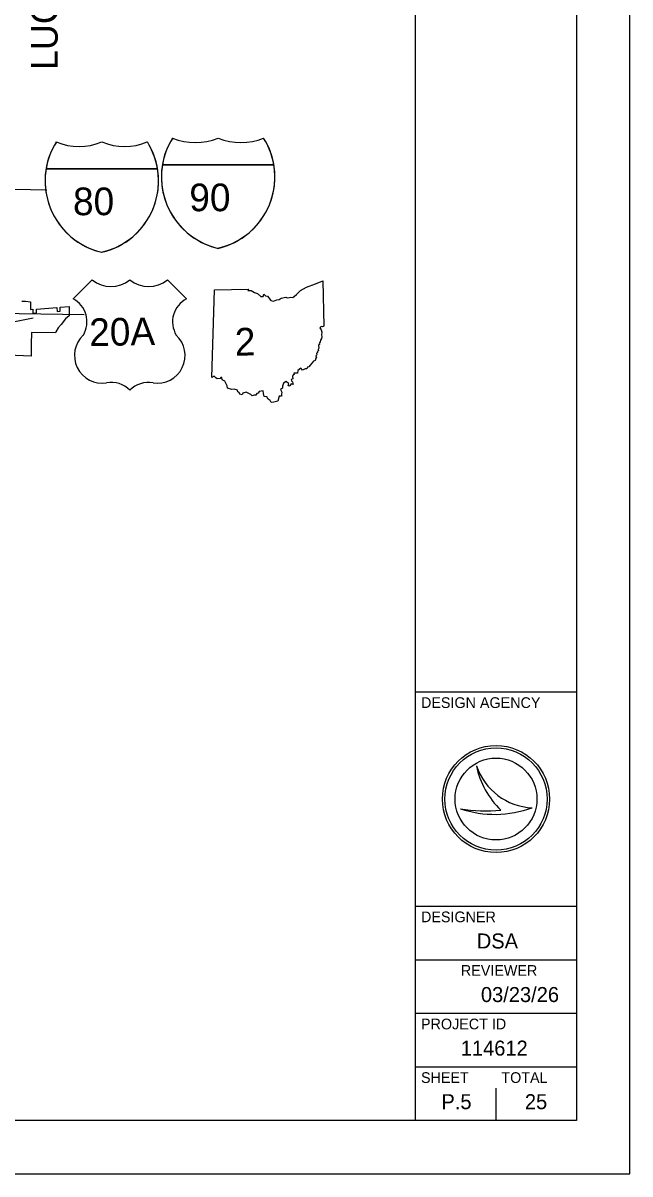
# Model space of a CAD drawing. Extents: x 0 to 849, y 0 to 440.
# Drawn here: x 566.7 to 680, y 0 to 214.9 of the extents above; entities that cross this region are included whole.
import ezdxf

# ---------------------------------------------------------------- set-up
doc = ezdxf.new("R2010")
doc.units = 0
for name, color, linetype in [('DV_X_Corp_Line', 7, 'Continuous'), ('GM_X_Adjacent_County_Text', 7, 'Continuous'), ('GM_X_Interstate_Route', 7, 'Continuous'), ('PV_P_Walk', 7, 'Continuous'), ('RD_X_RR_2', 7, 'Continuous'), ('SH_Border', 7, 'Continuous'), ('SH_Cut_Line', 7, 'Continuous'), ('SH_Data', 7, 'Continuous')]:
    doc.layers.add(name, color=color, linetype=linetype)

msp = doc.modelspace()

# ---------------------------------------------------------------- linework, layer by layer
at = {"layer": 'DV_X_Corp_Line'}
msp.add_lwpolyline([(566.48, 162.95), (567.15, 162.94), (568.14, 162.83), (568.14, 161.4), (568.57, 161.43), (568.56, 160.72), (569.22, 160.79), (569.23, 161.48), (573.02, 161.79), (573.07, 161.04), (573.63, 161.08), (573.62, 161.83), (575.3, 161.96), (575.35, 160.22), (574.62, 159.66), (573.81, 158.59), (573.26, 157.94), (572.82, 157.24), (572.76, 157.04), (568.3, 157.09), (568.26, 154.94), (568.24, 152.7), (563.91, 152.84)], dxfattribs=at)
at = {"layer": 'GM_X_Interstate_Route'}
for p, q in [((560.35, 183.93), (571.18, 183.73)), ((559.94, 160.75), (578.12, 160.49))]:
    msp.add_line(p, q, dxfattribs=at)
at = {"layer": 'PV_P_Walk'}
for p, q in [((571.02, 187.68), (591.82, 187.68)), ((591.82, 187.68), (571.02, 187.68)), ((591.82, 187.68), (571.02, 187.68)), ((592.74, 188.42), (613.54, 188.42)), ((613.54, 188.42), (592.74, 188.42)), ((613.54, 188.42), (592.74, 188.42)), ((579.6, 166.92), (576.05, 163.38)), ((579.6, 166.92), (576.05, 163.38)), ((597.24, 163.38), (593.69, 166.92)), ((597.24, 163.38), (593.69, 166.92)), ((601.97, 148.68), (602.43, 165.05)), ((601.97, 148.68), (602.43, 165.05))]:
    msp.add_line(p, q, dxfattribs=at)
for points in [[(602.43, 165.05), (608.78, 165.16), (608.68, 164.96), (609.28, 164.92), (609.92, 164.57), (610.46, 164.35), (611.12, 163.83), (611.51, 163.83), (611.68, 164.26), (611.98, 163.93), (612.34, 163.87), (612.96, 163.09), (613.47, 162.92), (614.08, 163.19), (614.54, 163.23), (614.87, 163.5), (615.75, 163.72), (615.99, 163.59), (616.45, 163.61), (616.68, 163.71), (617.08, 163.62), (617.79, 164.22), (618.52, 164.92), (619.64, 165.58), (621.32, 166.21), (622.65, 166.77), (622.84, 158.28)], [(602.43, 165.05), (608.78, 165.16), (608.68, 164.96), (609.28, 164.92), (609.92, 164.57), (610.46, 164.35), (611.12, 163.83), (611.51, 163.83), (611.68, 164.26), (611.98, 163.93), (612.34, 163.87), (612.96, 163.09), (613.47, 162.92), (614.08, 163.19), (614.54, 163.23), (614.87, 163.5), (615.75, 163.72), (615.99, 163.59), (616.45, 163.61), (616.68, 163.71), (617.08, 163.62), (617.79, 164.22), (618.52, 164.92), (619.64, 165.58), (621.32, 166.21), (622.65, 166.77), (622.84, 158.28)], [(622.84, 158.28), (622.64, 158.16), (622.34, 158.21), (622.13, 157.97), (622.39, 157.58), (622.51, 157.16), (622.4, 156.69), (622.5, 156.31), (622.43, 155.99), (622.24, 155.67), (622.18, 155.37), (622.01, 155.05), (622.03, 154.87), (621.87, 154.73), (621.9, 154.2), (621.82, 153.91), (621.85, 153.65), (621.6, 153.58), (621.65, 153.37), (621.49, 153.21), (621.53, 152.93), (621.35, 152.76), (621.52, 152.4), (621.38, 152.29), (621.26, 151.85), (620.94, 151.76), (620.3, 150.97), (620.07, 150.67), (619.81, 150.6), (619.67, 150.29), (619.36, 150.29), (618.88, 150.07), (618.57, 150.44), (618.03, 150), (617.97, 149.49), (617.28, 149.51), (617.31, 149.25), (617.16, 149.17), (617.02, 148.91), (617.1, 148.45), (616.78, 148.34), (616.82, 148.07), (617.02, 147.91), (617.11, 147.4), (616.77, 147.5), (616.5, 147.07), (616.21, 147.17), (616.3, 147.54), (615.82, 147.97), (615.36, 147.62), (615.12, 147.06), (615.12, 146.69), (614.78, 146.46), (615, 145.93), (614.96, 145.56), (614.96, 145.21), (614.54, 145.22), (614.28, 144.28)], [(622.84, 158.28), (622.64, 158.16), (622.34, 158.21), (622.13, 157.97), (622.39, 157.58), (622.51, 157.16), (622.4, 156.69), (622.5, 156.31), (622.43, 155.99), (622.24, 155.67), (622.18, 155.37), (622.01, 155.05), (622.03, 154.87), (621.87, 154.73), (621.9, 154.2), (621.82, 153.91), (621.85, 153.65), (621.6, 153.58), (621.65, 153.37), (621.49, 153.21), (621.53, 152.93), (621.35, 152.76), (621.52, 152.4), (621.38, 152.29), (621.26, 151.85), (620.94, 151.76), (620.3, 150.97), (620.07, 150.67), (619.81, 150.6), (619.67, 150.29), (619.36, 150.29), (618.88, 150.07), (618.57, 150.44), (618.03, 150), (617.97, 149.49), (617.28, 149.51), (617.31, 149.25), (617.16, 149.17), (617.02, 148.91), (617.1, 148.45), (616.78, 148.34), (616.82, 148.07), (617.02, 147.91), (617.11, 147.4), (616.77, 147.5), (616.5, 147.07), (616.21, 147.17), (616.3, 147.54), (615.82, 147.97), (615.36, 147.62), (615.12, 147.06), (615.12, 146.69), (614.78, 146.46), (615, 145.93), (614.96, 145.56), (614.96, 145.21), (614.54, 145.22), (614.28, 144.28)], [(614.28, 144.28), (613.54, 144.1), (613.02, 144), (612.84, 144.42), (612.47, 144.65), (612.23, 145.08), (611.71, 145.14), (611.58, 145.73), (611.52, 146.21), (610.8, 146.09), (610.6, 145.79), (610.34, 145.72), (610.2, 145.42), (609.85, 145.4), (609.47, 145.26), (609.23, 145.55), (608.61, 145.84), (608.34, 145.99), (607.76, 145.75), (607.63, 145.48), (607.18, 145.6), (607.07, 145.91), (606.79, 146), (606.73, 146.33), (606.13, 146.5), (605.68, 146.43), (604.88, 146.69), (604.83, 147.12), (604.56, 147.64), (604.41, 148.01), (603.91, 148.28), (603.8, 148.72), (603.64, 148.7), (603.49, 148.53), (602.93, 148.45), (602.7, 148.62), (602.39, 148.93), (601.97, 148.68)], [(614.28, 144.28), (613.54, 144.1), (613.02, 144), (612.84, 144.42), (612.47, 144.65), (612.23, 145.08), (611.71, 145.14), (611.58, 145.73), (611.52, 146.21), (610.8, 146.09), (610.6, 145.79), (610.34, 145.72), (610.2, 145.42), (609.85, 145.4), (609.47, 145.26), (609.23, 145.55), (608.61, 145.84), (608.34, 145.99), (607.76, 145.75), (607.63, 145.48), (607.18, 145.6), (607.07, 145.91), (606.79, 146), (606.73, 146.33), (606.13, 146.5), (605.68, 146.43), (604.88, 146.69), (604.83, 147.12), (604.56, 147.64), (604.41, 148.01), (603.91, 148.28), (603.8, 148.72), (603.64, 148.7), (603.49, 148.53), (602.93, 148.45), (602.7, 148.62), (602.39, 148.93), (601.97, 148.68)]]:
    msp.add_lwpolyline(points, dxfattribs=at)
for centre, radius, start, end in [((606.21, 186.13), 13.67, 147.8216, 256.9941), ((605.36, 186.37), 12.79, 146.654, 170.759), ((598.89, 203.46), 10.91, 247.0848, 292.9105), ((598.89, 203.46), 10.91, 247.0848, 292.9105), ((600.06, 186.13), 13.67, 283.0065, 32.1787), ((607.38, 203.46), 10.91, 247.0916, 292.9084), ((607.38, 203.46), 10.91, 247.0916, 292.9084), ((600.06, 186.13), 13.67, 9.6475, 32.179), ((584.5, 185.39), 13.67, 147.8216, 256.9941), ((583.64, 185.63), 12.79, 146.654, 170.759), ((577.18, 202.72), 10.91, 247.0848, 292.9105), ((577.18, 202.72), 10.91, 247.0848, 292.9105), ((578.35, 185.39), 13.67, 283.0065, 32.1787), ((585.67, 202.72), 10.91, 247.0916, 292.9084), ((585.67, 202.72), 10.91, 247.0916, 292.9084), ((578.35, 185.39), 13.67, 9.6475, 32.179), ((584.5, 185.39), 13.67, 170.3514, 256.9967), ((578.38, 185.39), 13.64, 282.7667, 9.6898), ((606.21, 186.13), 13.67, 170.3514, 256.9967), ((600.09, 186.13), 13.64, 282.7667, 9.6898), ((583.12, 171.4), 5.7, 231.813, 308.187), ((583.12, 171.4), 5.7, 231.813, 308.187), ((590.17, 171.4), 5.7, 231.813, 308.187), ((590.17, 171.4), 5.7, 231.813, 308.187), ((573.84, 159.1), 4.82, 329.1175, 62.6108), ((573.84, 159.1), 4.82, 329.1175, 62.6108), ((599.45, 159.1), 4.82, 117.3892, 210.8825), ((599.45, 159.1), 4.82, 117.3892, 210.8825), ((581.52, 152.82), 5.2, 133.0046, 278.7282), ((581.52, 152.82), 5.2, 133.0046, 278.7282), ((591.77, 152.82), 5.2, 261.2718, 46.9954), ((591.77, 152.82), 5.2, 261.2718, 46.9954), ((583.27, 143.13), 4.65, 43.4177, 101.8742), ((583.27, 143.13), 4.65, 43.4177, 101.8742), ((590.12, 142.82), 4.94, 79.9613, 134.7468), ((590.12, 142.82), 4.94, 79.9613, 134.7468)]:
    msp.add_arc(centre, radius, start, end, dxfattribs=at)
at = {"layer": 'RD_X_RR_2'}
msp.add_lwpolyline([(568.63, 159.76), (514.51, 148.98), (454.53, 137.13), (454.61, 137.13)], dxfattribs=at)
at = {"layer": 'SH_Border'}
for p, q in [((640, 10), (640, 430)), ((640, 90), (670, 90)), ((640, 50), (670, 50)), ((640, 40), (670, 40)), ((640, 30), (670, 30)), ((640, 20), (670, 20))]:
    msp.add_line(p, q, dxfattribs=at)
msp.add_lwpolyline([(30, 430), (670, 430), (670, 10), (30, 10)], close=True, dxfattribs=at)
at = {"layer": 'SH_Cut_Line'}
msp.add_lwpolyline([(0, 0), (680, 0), (680, 440), (0, 440)], close=True, dxfattribs=at)
at = {"layer": 'SH_Data'}
for p, q in [((651.35, 76.19), (651.35, 76.19)), ((655, 70), (655, 70)), ((648.34, 68.19), (648.34, 68.19)), ((661.75, 68.37), (661.75, 68.37)), ((655, 10), (655, 16)), ((647.5, 13.5), (647.5, 13.5))]:
    msp.add_line(p, q, dxfattribs=at)
for radius in [10, 9.54, 9.54, 7.64]:
    msp.add_circle((655, 70), radius, dxfattribs=at)
for centre, radius, start, end in [((662.32, 79.95), 11.6, 198.9257, 198.9319), ((666.93, 79.4), 15.91, 191.6379, 191.6421), ((662.32, 79.95), 11.6, 198.9319, 267.1657), ((666.93, 79.4), 15.91, 191.6421, 226.0947), ((654.79, 87.4), 20.26, 251.4576, 290.0832), ((652.96, 93.09), 25.32, 259.4964, 259.4995), ((654.79, 87.4), 20.26, 251.4527, 251.4576), ((652.96, 93.09), 25.32, 259.4995, 276.6672)]:
    msp.add_arc(centre, radius, start, end, dxfattribs=at)

# ---------------------------------------------------------------- texts
at = {"layer": 'GM_X_Adjacent_County_Text'}
msp.add_text('LUCAS  COUNTY', height=5.0058, rotation=90.0231, dxfattribs=at).set_placement((573.19, 206.11))
at = {"layer": 'PV_P_Walk'}
for s, rotation, p in [('90', 360, (597.76, 179.74)), ('80', 360, (576.05, 179)), ('20A', 1.0142, (579.12, 154.55)), (' 2 ', 1.0142, (604.37, 152.73))]:
    msp.add_text(s, height=5.162, rotation=rotation, dxfattribs=at).set_placement(p)
at = {"layer": 'SH_Data'}
for s, height, p in [('DESIGN AGENCY', 2, (641, 87)), ('DESIGNER', 2, (641, 47)), ('DSA', 2.8, (651.41, 42.1)), ('REVIEWER', 2, (648.44, 37)), ('03/23/26', 2.8, (652.18, 32.1)), ('PROJECT ID', 2, (641, 27)), ('114612', 2.8, (648.42, 22.1)), ('SHEET', 2, (641, 17)), ('TOTAL', 2, (656, 17)), ('P.5', 2.8, (644.81, 12.1)), ('25', 2.8, (660.39, 12.1))]:
    msp.add_text(s, height=height, dxfattribs=at).set_placement(p)

doc.saveas('drawing.dxf')
